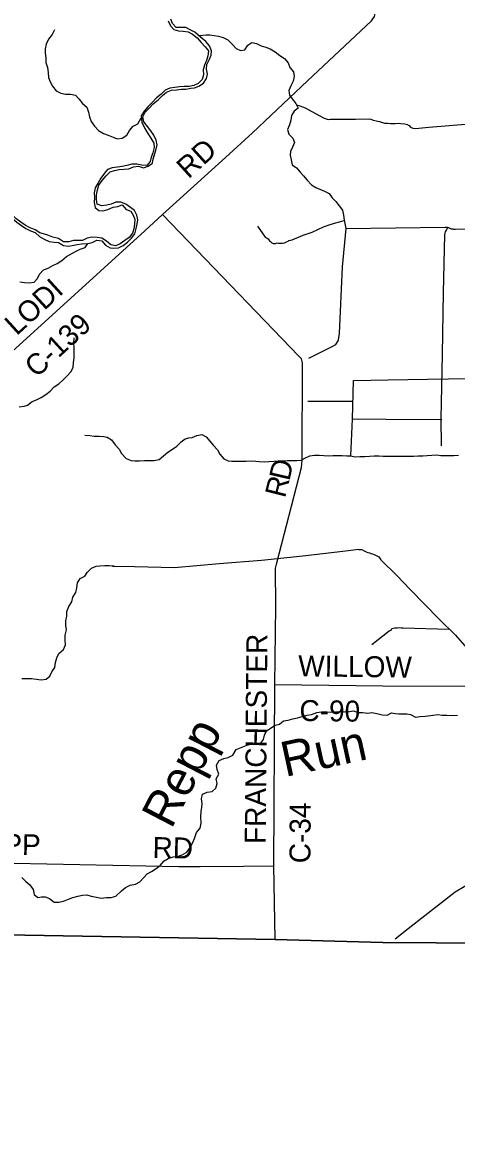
# Model space of a CAD drawing. Extents: x 1985906 to 2277390, y 930619 to 1324581.
# Drawn here: x 2092990 to 2099199, y 1086662 to 1102819 of the extents above; entities that cross this region are included whole.
import ezdxf

# ---------------------------------------------------------------- set-up
doc = ezdxf.new("R2010")
doc.units = 0
for name, color, linetype in [('GM_X_Adjacent_County', 7, 'Continuous'), ('GM_X_County', 7, 'Continuous'), ('GM_X_County_Road', 7, 'Continuous'), ('GM_X_County_Road_Text', 7, 'Continuous'), ('GM_X_Interstate_Route', 7, 'Continuous'), ('GM_X_Minor_River', 7, 'Continuous'), ('GM_X_Minor_River_Text', 7, 'Continuous'), ('GM_X_Township', 7, 'Continuous'), ('GM_X_Township_Road', 7, 'Continuous'), ('GM_X_Township_Road_Text', 7, 'Continuous')]:
    doc.layers.add(name, color=color, linetype=linetype)

msp = doc.modelspace()

# ---------------------------------------------------------------- linework, layer by layer
at = {"layer": 'GM_X_Adjacent_County'}
msp.add_lwpolyline([(2071304, 1070160), (2071255, 1071444), (2071122, 1077956), (2071119, 1078116), (2071029, 1081482), (2070976, 1083468), (2070964, 1084056), (2070912, 1086527), (2070832, 1090054), (2071379, 1090059), (2072192, 1090056), (2076166, 1089991), (2079513, 1089939), (2083903, 1089896), (2084803, 1089885), (2084868, 1089884), (2091363, 1089786), (2096607, 1089693), (2098147, 1089654), (2105015, 1089609), (2106583, 1089599), (2107472, 1089594), (2107997, 1089591), (2112770, 1089563)], dxfattribs=at)
at = {"layer": 'GM_X_County'}
msp.add_lwpolyline([(2066117, 1090095), (2068677, 1090072), (2070832, 1090054), (2071379, 1090059), (2072192, 1090056), (2076166, 1089991), (2079513, 1089939), (2083903, 1089896), (2084803, 1089885), (2084868, 1089884), (2091363, 1089786), (2096607, 1089693), (2098147, 1089654), (2105015, 1089609), (2106583, 1089599), (2107472, 1089594), (2107997, 1089591), (2112770, 1089563)], dxfattribs=at)
at = {"layer": 'GM_X_County_Road'}
for points in [[(2092836, 1098107), (2094738, 1099840), (2094992, 1100073), (2095892, 1100888), (2096280, 1101240), (2097066, 1101987), (2097986, 1102846), (2098028, 1102904), (2098040, 1102974)], [(2096606, 1089699), (2096584, 1090747), (2096602, 1093346), (2096616, 1094461), (2096612, 1095008), (2096624, 1095069), (2096980, 1096451), (2096992, 1096556), (2096995, 1097950), (2096984, 1098006), (2096946, 1098046), (2094992, 1100073)], [(2096602, 1093346), (2098144, 1093324), (2099312, 1093322), (2099808, 1093338), (2100235, 1093343), (2101341, 1093348), (2104944, 1093359), (2106580, 1093367), (2107583, 1093382)]]:
    msp.add_lwpolyline(points, dxfattribs=at)
at = {"layer": 'GM_X_Interstate_Route'}
msp.add_lwpolyline([(2098323, 1089703), (2098508, 1089851), (2099180, 1090376), (2099823, 1090761), (2100500, 1091095), (2101112, 1091363), (2101799, 1091594), (2102541, 1091805), (2103302, 1091971), (2103985, 1092086), (2104506, 1092133), (2104949, 1092148), (2105579, 1092170), (2106733, 1092238), (2106890, 1092241), (2107570, 1092271)], dxfattribs=at)
at = {"layer": 'GM_X_Minor_River'}
for points in [[(2095072, 1102842), (2095107, 1102774), (2095155, 1102718), (2095220, 1102702), (2095290, 1102695), (2095358, 1102689), (2095421, 1102652), (2095487, 1102600), (2095546, 1102536), (2095601, 1102472), (2095652, 1102413), (2095642, 1102344), (2095623, 1102276), (2095593, 1102211), (2095576, 1102143), (2095578, 1102071), (2095559, 1102002), (2095503, 1101948), (2095439, 1101919), (2095373, 1101903), (2095301, 1101904), (2095235, 1101898), (2095171, 1101891), (2095098, 1101880), (2095032, 1101850), (2094971, 1101795), (2094905, 1101742), (2094843, 1101676), (2094788, 1101619), (2094732, 1101552), (2094688, 1101486), (2094695, 1101393)], [(2095072, 1102842), (2095107, 1102774), (2095155, 1102718), (2095220, 1102702), (2095290, 1102695), (2095358, 1102689), (2095421, 1102652), (2095487, 1102600), (2095546, 1102536), (2095601, 1102472), (2095652, 1102413), (2095642, 1102344), (2095623, 1102276), (2095593, 1102211), (2095576, 1102143), (2095578, 1102071), (2095559, 1102002), (2095503, 1101948), (2095439, 1101919), (2095373, 1101903), (2095301, 1101904), (2095235, 1101898), (2095171, 1101891), (2095098, 1101880), (2095032, 1101850), (2094971, 1101795), (2094905, 1101742), (2094843, 1101676), (2094788, 1101619), (2094732, 1101552), (2094688, 1101486), (2094695, 1101390)], [(2095543, 1102604), (2095457, 1102680), (2095390, 1102716), (2095328, 1102747), (2095255, 1102747), (2095189, 1102748), (2095134, 1102804), (2095112, 1102870)], [(2095532, 1102614), (2095457, 1102680), (2095390, 1102716), (2095328, 1102747), (2095255, 1102747), (2095189, 1102748), (2095134, 1102804), (2095112, 1102870)], [(2093448, 1102713), (2093414, 1102648), (2093359, 1102580), (2093327, 1102509), (2093312, 1102443), (2093312, 1102388), (2093321, 1102316), (2093321, 1102248), (2093344, 1102176), (2093356, 1102103), (2093363, 1102035), (2093386, 1101973), (2093418, 1101909), (2093471, 1101841), (2093536, 1101809), (2093604, 1101796), (2093676, 1101794), (2093745, 1101781), (2093797, 1101727), (2093846, 1101661), (2093909, 1101607), (2093933, 1101535), (2093946, 1101471), (2093971, 1101403), (2094019, 1101335), (2094078, 1101273), (2094147, 1101231), (2094213, 1101207), (2094284, 1101178), (2094344, 1101154), (2094416, 1101167), (2094480, 1101209), (2094522, 1101276), (2094574, 1101337), (2094640, 1101371), (2094689, 1101458)], [(2094896, 1100989), (2094915, 1101068), (2094904, 1101138), (2094869, 1101206), (2094827, 1101272), (2094776, 1101334), (2094725, 1101400), (2094709, 1101468), (2094746, 1101539), (2094802, 1101593), (2094861, 1101658), (2094929, 1101715), (2094991, 1101775), (2095051, 1101824), (2095119, 1101850), (2095191, 1101857), (2095259, 1101864), (2095327, 1101868), (2095397, 1101879), (2095448, 1101887), (2095512, 1101908), (2095581, 1101952), (2095623, 1102017), (2095635, 1102083), (2095624, 1102151), (2095629, 1102218), (2095665, 1102296), (2095688, 1102353), (2095694, 1102417), (2095667, 1102487), (2095612, 1102549), (2095532, 1102613)], [(2094896, 1100988), (2094915, 1101068), (2094904, 1101138), (2094869, 1101206), (2094827, 1101272), (2094776, 1101334), (2094725, 1101400), (2094709, 1101468), (2094746, 1101539), (2094802, 1101593), (2094861, 1101658), (2094929, 1101715), (2094991, 1101775), (2095051, 1101824), (2095119, 1101850), (2095191, 1101857), (2095259, 1101864), (2095327, 1101868), (2095397, 1101879), (2095448, 1101887), (2095512, 1101908), (2095581, 1101952), (2095623, 1102017), (2095635, 1102083), (2095624, 1102151), (2095629, 1102218), (2095665, 1102296), (2095688, 1102353), (2095694, 1102417), (2095667, 1102487), (2095612, 1102549), (2095543, 1102604)], [(2095517, 1102636), (2095615, 1102642), (2095668, 1102643), (2095732, 1102636), (2095794, 1102624), (2095860, 1102605), (2095926, 1102574), (2095989, 1102512), (2096048, 1102447), (2096110, 1102420), (2096173, 1102430), (2096216, 1102496), (2096269, 1102533), (2096337, 1102522), (2096403, 1102488), (2096469, 1102467), (2096535, 1102442), (2096606, 1102402), (2096670, 1102347), (2096737, 1102303), (2096792, 1102244), (2096817, 1102177), (2096867, 1102116), (2096875, 1102048), (2096862, 1101980), (2096831, 1101916), (2096801, 1101848), (2096812, 1101782), (2096848, 1101727), (2096901, 1101662), (2096932, 1101593), (2096879, 1101550), (2096839, 1101490), (2096830, 1101424), (2096809, 1101354), (2096781, 1101289), (2096802, 1101224), (2096860, 1101167), (2096881, 1101102), (2096853, 1101038), (2096824, 1100973), (2096821, 1100923), (2096836, 1100854), (2096849, 1100782), (2096912, 1100738), (2096965, 1100677), (2097011, 1100626), (2097064, 1100565), (2097125, 1100499), (2097189, 1100460), (2097253, 1100431), (2097312, 1100405), (2097380, 1100374), (2097421, 1100313), (2097471, 1100260), (2097522, 1100197), (2097567, 1100134), (2097584, 1100063), (2097594, 1099993), (2097614, 1099870)], [(2096912, 1101640), (2096956, 1101627), (2097036, 1101601), (2097287, 1101462), (2097307, 1101453), (2097333, 1101441), (2097363, 1101432), (2097397, 1101436), (2097399, 1101438), (2097753, 1101435), (2097940, 1101441), (2097974, 1101435), (2098008, 1101424), (2098050, 1101415), (2098098, 1101402), (2098142, 1101391), (2098172, 1101379), (2098222, 1101378), (2098254, 1101375), (2098289, 1101374), (2098323, 1101376), (2098371, 1101379), (2098405, 1101376), (2098461, 1101369), (2098497, 1101358), (2098509, 1101352), (2098525, 1101344), (2098541, 1101321), (2098575, 1101309), (2098615, 1101304), (2098802, 1101322), (2099678, 1101394)], [(2094695, 1101393), (2094738, 1101302), (2094783, 1101232), (2094824, 1101164), (2094868, 1101094), (2094873, 1101030), (2094854, 1100957), (2094830, 1100895), (2094815, 1100833), (2094767, 1100774), (2094695, 1100779), (2094626, 1100791), (2094554, 1100792), (2094482, 1100772), (2094416, 1100759), (2094348, 1100751), (2094273, 1100742), (2094207, 1100717), (2094160, 1100663), (2094112, 1100594), (2094071, 1100526), (2094029, 1100455), (2094014, 1100383), (2094018, 1100315), (2094015, 1100242), (2094028, 1100170), (2094082, 1100128), (2094144, 1100125), (2094212, 1100143), (2094284, 1100176), (2094353, 1100185), (2094415, 1100211), (2094471, 1100143), (2094538, 1100120), (2094577, 1100052), (2094595, 1100002), (2094592, 1099934), (2094582, 1099869), (2094563, 1099803), (2094515, 1099742), (2094453, 1099702), (2094385, 1099653), (2094323, 1099624), (2094251, 1099636), (2094190, 1099692), (2094124, 1099735), (2094055, 1099745), (2093983, 1099750), (2093915, 1099734), (2093849, 1099699), (2093783, 1099699), (2093717, 1099700), (2093650, 1099680), (2093574, 1099683), (2093505, 1099729), (2093421, 1099747)], [(2094696, 1101391), (2094738, 1101302), (2094783, 1101232), (2094824, 1101164), (2094868, 1101094), (2094873, 1101030), (2094854, 1100957), (2094830, 1100895), (2094815, 1100833), (2094767, 1100774), (2094695, 1100779), (2094626, 1100791), (2094554, 1100792), (2094482, 1100772), (2094416, 1100759), (2094348, 1100751), (2094273, 1100742), (2094207, 1100717), (2094160, 1100663), (2094112, 1100594), (2094071, 1100526), (2094029, 1100455), (2094014, 1100383), (2094018, 1100315), (2094015, 1100242), (2094028, 1100170), (2094082, 1100128), (2094144, 1100125), (2094212, 1100143), (2094284, 1100176), (2094353, 1100185), (2094415, 1100211), (2094471, 1100143), (2094538, 1100120), (2094577, 1100052), (2094595, 1100002), (2094592, 1099934), (2094582, 1099869), (2094563, 1099803), (2094515, 1099742), (2094453, 1099702), (2094385, 1099653), (2094323, 1099624), (2094251, 1099636), (2094190, 1099692), (2094124, 1099735), (2094055, 1099745), (2093983, 1099750), (2093915, 1099734), (2093849, 1099699), (2093783, 1099699), (2093717, 1099700), (2093650, 1099680), (2093574, 1099683), (2093505, 1099729), (2093421, 1099747)], [(2093926, 1099659), (2093986, 1099670), (2094054, 1099707), (2094124, 1099693), (2094177, 1099631), (2094241, 1099596), (2094292, 1099588), (2094364, 1099595), (2094428, 1099627), (2094489, 1099678), (2094549, 1099733), (2094597, 1099797), (2094614, 1099870), (2094632, 1099932), (2094637, 1099996), (2094625, 1100062), (2094590, 1100130), (2094535, 1100172), (2094467, 1100218), (2094398, 1100251), (2094326, 1100249), (2094258, 1100222), (2094196, 1100206), (2094124, 1100195), (2094059, 1100219), (2094049, 1100285), (2094046, 1100355), (2094063, 1100423), (2094083, 1100492), (2094130, 1100558), (2094186, 1100625), (2094244, 1100682), (2094306, 1100702), (2094374, 1100715), (2094446, 1100719), (2094510, 1100728), (2094576, 1100756), (2094647, 1100765), (2094719, 1100739), (2094785, 1100764), (2094847, 1100805), (2094858, 1100867), (2094897, 1100991)], [(2093926, 1099659), (2093986, 1099670), (2094054, 1099707), (2094124, 1099693), (2094177, 1099631), (2094241, 1099596), (2094292, 1099588), (2094364, 1099595), (2094428, 1099627), (2094489, 1099678), (2094549, 1099733), (2094597, 1099797), (2094614, 1099870), (2094632, 1099932), (2094637, 1099996), (2094625, 1100062), (2094590, 1100130), (2094535, 1100172), (2094467, 1100218), (2094398, 1100251), (2094326, 1100249), (2094258, 1100222), (2094196, 1100206), (2094124, 1100195), (2094059, 1100219), (2094049, 1100285), (2094046, 1100355), (2094063, 1100423), (2094083, 1100492), (2094130, 1100558), (2094186, 1100625), (2094244, 1100682), (2094306, 1100702), (2094374, 1100715), (2094446, 1100719), (2094510, 1100728), (2094576, 1100756), (2094647, 1100765), (2094719, 1100739), (2094785, 1100764), (2094847, 1100805), (2094858, 1100867), (2094896, 1100988)], [(2093422, 1099748), (2093353, 1099776), (2093302, 1099789), (2093236, 1099811), (2093169, 1099854), (2093099, 1099880), (2093028, 1099918), (2092964, 1099961), (2092895, 1100017), (2092830, 1100075), (2092763, 1100128), (2092703, 1100182), (2092634, 1100198), (2092564, 1100225), (2092491, 1100269), (2092419, 1100278), (2092353, 1100262), (2092291, 1100243), (2092223, 1100211), (2092127, 1100223)], [(2093421, 1099747), (2093353, 1099776), (2093302, 1099789), (2093236, 1099811), (2093169, 1099854), (2093099, 1099880), (2093028, 1099918), (2092964, 1099961), (2092895, 1100017), (2092830, 1100075), (2092763, 1100128), (2092703, 1100182), (2092634, 1100198), (2092564, 1100225), (2092491, 1100269), (2092419, 1100278), (2092353, 1100262), (2092291, 1100243), (2092223, 1100211), (2092134, 1100222)], [(2092780, 1100058), (2092843, 1100013), (2092907, 1099963), (2092972, 1099915), (2093035, 1099874), (2093103, 1099840), (2093170, 1099816), (2093232, 1099755), (2093301, 1099717), (2093369, 1099685), (2093440, 1099678), (2093504, 1099670), (2093577, 1099629), (2093649, 1099621), (2093699, 1099626), (2093769, 1099642), (2093833, 1099651), (2093926, 1099659)], [(2092780, 1100058), (2092843, 1100013), (2092907, 1099963), (2092972, 1099915), (2093035, 1099874), (2093103, 1099840), (2093170, 1099816), (2093232, 1099755), (2093301, 1099717), (2093369, 1099685), (2093440, 1099678), (2093504, 1099670), (2093577, 1099629), (2093649, 1099621), (2093699, 1099626), (2093769, 1099642), (2093833, 1099651), (2093925, 1099659)], [(2096351, 1099904), (2096464, 1099749), (2096490, 1099733), (2096506, 1099722), (2096524, 1099694), (2096536, 1099684), (2096559, 1099667), (2096575, 1099659), (2096583, 1099655), (2096609, 1099656), (2096632, 1099666), (2096646, 1099663), (2096672, 1099661), (2096708, 1099660), (2096738, 1099668), (2096767, 1099679), (2096789, 1099691), (2096801, 1099701), (2096850, 1099710), (2097004, 1099777), (2097135, 1099821), (2097297, 1099896), (2097378, 1099924), (2097453, 1099947), (2097526, 1099966), (2097594, 1099987)], [(2097085, 1098015), (2097411, 1098176), (2097472, 1098213), (2097507, 1098262), (2097512, 1098280), (2097525, 1098368), (2097570, 1099323), (2097620, 1099874)], [(2097614, 1099874), (2099040, 1099891), (2099068, 1099892), (2099078, 1099886), (2099096, 1099882), (2099104, 1099876), (2099126, 1099867), (2099150, 1099865), (2099158, 1099864), (2099180, 1099860), (2099747, 1099881), (2101358, 1099909), (2101370, 1099911), (2101386, 1099906), (2101404, 1099904), (2101424, 1099900), (2101438, 1099875), (2101438, 1099863), (2101431, 1099837), (2101431, 1099813), (2101422, 1099779), (2101422, 1099761), (2101427, 1099739)], [(2098986, 1096761), (2098981, 1097146), (2098999, 1098071), (2099015, 1098958), (2099032, 1099779), (2099038, 1099805), (2099045, 1099824), (2099057, 1099850), (2099072, 1099876), (2099090, 1099884)], [(2092949, 1099106), (2093017, 1099099), (2093086, 1099095), (2093154, 1099102), (2093201, 1099154), (2093231, 1099217), (2093291, 1099279), (2093355, 1099306), (2093425, 1099343), (2093487, 1099373), (2093550, 1099412), (2093616, 1099471), (2093748, 1099544), (2093816, 1099576), (2093884, 1099601), (2093926, 1099659)], [(2092943, 1097317), (2093011, 1097327), (2093061, 1097344), (2093125, 1097396), (2093187, 1097421), (2093255, 1097454), (2093323, 1097494), (2093383, 1097545), (2093441, 1097606), (2093509, 1097647), (2093569, 1097707), (2093626, 1097762), (2093680, 1097821), (2093712, 1097883), (2093719, 1097956), (2093729, 1098020), (2093726, 1098092), (2093728, 1098165), (2093723, 1098237), (2093730, 1098306)], [(2097728, 1097694), (2098221, 1097707), (2098784, 1097716), (2099088, 1097720), (2099697, 1097723), (2100499, 1097743), (2101371, 1097731)], [(2097689, 1096619), (2097712, 1097144), (2097728, 1097694)], [(2097072, 1097401), (2097707, 1097399)], [(2097702, 1097146), (2098189, 1097145), (2098991, 1097140)], [(2093883, 1096914), (2093951, 1096907), (2094015, 1096898), (2094084, 1096898), (2094152, 1096893), (2094202, 1096886), (2094262, 1096845), (2094313, 1096777), (2094374, 1096712), (2094407, 1096649), (2094470, 1096582), (2094544, 1096550), (2094594, 1096545), (2094662, 1096546), (2094737, 1096551), (2094805, 1096553), (2094871, 1096552), (2094944, 1096567), (2095009, 1096616), (2095067, 1096669), (2095134, 1096712), (2095197, 1096757), (2095258, 1096816), (2095317, 1096861), (2095368, 1096874), (2095418, 1096879), (2095485, 1096908), (2095556, 1096924), (2095617, 1096889), (2095672, 1096826), (2095722, 1096765), (2095779, 1096703), (2095812, 1096640), (2095871, 1096577), (2095933, 1096548), (2095983, 1096541), (2096049, 1096542), (2096120, 1096540), (2096190, 1096541), (2096262, 1096546), (2096327, 1096542), (2096377, 1096537), (2096451, 1096534), (2096516, 1096537), (2096586, 1096543), (2096648, 1096544), (2096717, 1096545), (2096783, 1096550), (2096843, 1096551), (2096914, 1096549), (2096978, 1096554), (2097041, 1096589), (2097102, 1096620), (2097168, 1096627), (2097233, 1096625), (2097301, 1096622), (2097367, 1096617), (2097436, 1096624), (2097500, 1096624), (2097564, 1096623), (2097631, 1096620), (2097681, 1096619), (2097749, 1096602), (2097819, 1096606), (2097888, 1096609), (2097954, 1096614), (2098023, 1096618), (2098087, 1096617), (2098153, 1096614), (2098270, 1096612), (2098332, 1096614), (2098511, 1096611), (2098583, 1096612), (2098652, 1096616), (2098720, 1096619), (2098779, 1096624), (2098845, 1096627), (2098913, 1096630), (2098978, 1096624), (2099163, 1096621), (2099229, 1096625)], [(2097338, 1096613), (2097339, 1096613)], [(2094278, 1095040), (2094591, 1095034), (2095166, 1095021), (2095804, 1095079), (2096410, 1095126), (2097000, 1095187), (2097572, 1095252), (2097802, 1095284), (2097804, 1095276), (2097844, 1095275), (2097878, 1095258), (2097906, 1095244), (2097930, 1095235), (2097956, 1095229), (2097976, 1095222), (2097998, 1095216), (2098020, 1095207), (2098039, 1095197), (2098071, 1095182), (2098091, 1095170), (2098119, 1095127), (2098344, 1094904), (2098537, 1094704), (2098954, 1094278), (2099185, 1094053), (2099349, 1093867)], [(2092978, 1093433), (2093119, 1093430), (2093187, 1093423), (2093256, 1093414), (2093326, 1093422), (2093381, 1093463), (2093408, 1093525), (2093450, 1093588), (2093461, 1093660), (2093480, 1093726), (2093509, 1093788), (2093573, 1093847), (2093604, 1093913), (2093599, 1093981), (2093599, 1094049), (2093616, 1094125), (2093607, 1094190), (2093608, 1094258), (2093622, 1094324), (2093623, 1094392), (2093650, 1094462), (2093694, 1094527), (2093711, 1094593), (2093750, 1094663), (2093768, 1094730), (2093777, 1094799), (2093812, 1094860), (2093881, 1094895), (2093916, 1094946), (2093974, 1095010), (2094042, 1095040), (2094097, 1095041), (2094167, 1095046), (2094229, 1095047), (2094300, 1095041)], [(2097990, 1093915), (2098235, 1094113), (2098266, 1094123), (2098276, 1094147), (2098292, 1094152), (2098320, 1094158), (2098351, 1094155), (2098379, 1094159), (2098407, 1094156), (2098439, 1094154), (2099090, 1094135)], [(2096046, 1092413), (2096120, 1092442), (2096192, 1092471), (2096265, 1092494), (2096332, 1092505), (2096394, 1092500), (2096437, 1092559), (2096454, 1092622), (2096481, 1092682), (2096604, 1092761), (2096668, 1092776), (2096724, 1092825), (2096790, 1092834), (2096857, 1092855), (2096923, 1092870), (2096991, 1092887), (2097061, 1092904), (2097127, 1092917), (2097203, 1092945), (2097269, 1092954), (2097347, 1092955), (2097398, 1092950), (2097470, 1092953), (2097522, 1092956), (2097594, 1092955), (2097668, 1092960), (2097726, 1092967), (2097789, 1092944), (2097857, 1092943), (2097931, 1092934), (2097987, 1092945), (2098062, 1092930), (2098138, 1092911), (2098209, 1092906), (2098270, 1092939), (2098327, 1092932), (2098377, 1092927), (2098427, 1092924), (2098489, 1092923), (2098540, 1092914), (2098614, 1092875), (2098680, 1092888), (2098751, 1092893), (2098867, 1092907)], [(2098861, 1092907), (2098931, 1092914), (2098993, 1092907), (2099063, 1092908), (2099131, 1092903), (2099214, 1092906)], [(2094323, 1090313), (2094404, 1090391), (2094461, 1090438), (2094531, 1090474), (2094605, 1090489), (2094670, 1090522), (2094725, 1090583), (2094775, 1090636), (2094836, 1090669), (2094900, 1090710), (2094961, 1090756), (2095015, 1090819), (2095072, 1090852), (2095144, 1090879), (2095206, 1090882), (2095276, 1090905), (2095340, 1090944), (2095389, 1091013), (2095420, 1091076), (2095449, 1091141), (2095481, 1091225), (2095531, 1091290), (2095545, 1091359), (2095542, 1091457), (2095547, 1091525), (2095556, 1091590), (2095559, 1091640), (2095552, 1091708), (2095567, 1091777), (2095633, 1091804), (2095703, 1091811), (2095756, 1091862), (2095775, 1091927), (2095762, 1091993), (2095797, 1092061), (2095776, 1092127), (2095765, 1092189), (2095802, 1092256), (2095868, 1092287), (2095934, 1092300), (2095997, 1092331), (2096045, 1092413)], [(2092978, 1090584), (2093035, 1090526), (2093092, 1090477), (2093139, 1090412), (2093157, 1090340), (2093210, 1090296), (2093262, 1090307), (2093312, 1090304), (2093376, 1090283), (2093443, 1090230), (2093509, 1090231), (2093575, 1090244), (2093645, 1090273), (2093711, 1090296), (2093781, 1090313), (2093845, 1090330), (2093909, 1090335), (2093973, 1090316), (2094046, 1090299), (2094114, 1090286), (2094190, 1090296), (2094257, 1090297), (2094323, 1090314)]]:
    msp.add_lwpolyline(points, dxfattribs=at)
at = {"layer": 'GM_X_Township'}
msp.add_lwpolyline([(2112770, 1089563), (2107997, 1089591), (2107472, 1089594), (2106583, 1089599), (2105015, 1089609), (2098147, 1089654), (2096607, 1089693), (2091363, 1089786)], dxfattribs=at)
at = {"layer": 'GM_X_Township_Road'}
msp.add_lwpolyline([(2091352, 1091013), (2091453, 1091004), (2091531, 1090970), (2091700, 1090862), (2091788, 1090822), (2091915, 1090809), (2095227, 1090740), (2095530, 1090739), (2096154, 1090743), (2096584, 1090747)], dxfattribs=at)

# ---------------------------------------------------------------- texts
at = {"layer": 'GM_X_County_Road_Text'}
for s, rotation, p in [('RD', 42.2068, (2095364, 1100573)), ('LODI', 42.3511, (2092904, 1098329)), ('C-139', 42.4594, (2093190, 1097725)), ('D', 76.9615, (2096807, 1096248)), ('R', 75.9751, (2096746, 1096004)), ('FRANCHESTER', 89.5163, (2096469, 1091061)), ('WILLOW', 359.3425, (2096933, 1093462)), ('C-90', 359.3129, (2096951, 1092823)), ('C-34', 89.6571, (2097109, 1090785))]:
    msp.add_text(s, height=300, rotation=rotation, dxfattribs=at).set_placement(p)
at = {"layer": 'GM_X_Minor_River_Text'}
for s, rotation, p in [('Repp', 62.5414, (2095118, 1091265)), ('Run', 12.1968, (2096748, 1092020))]:
    msp.add_text(s, height=500.2, rotation=rotation, dxfattribs=at).set_placement(p)
at = {"layer": 'GM_X_Township_Road_Text'}
for s, rotation, p in [('REPP', 358.8491, (2092154, 1090920)), ('RD', 359.0248, (2094848, 1090862))]:
    msp.add_text(s, height=300, rotation=rotation, dxfattribs=at).set_placement(p)

doc.saveas('drawing.dxf')
